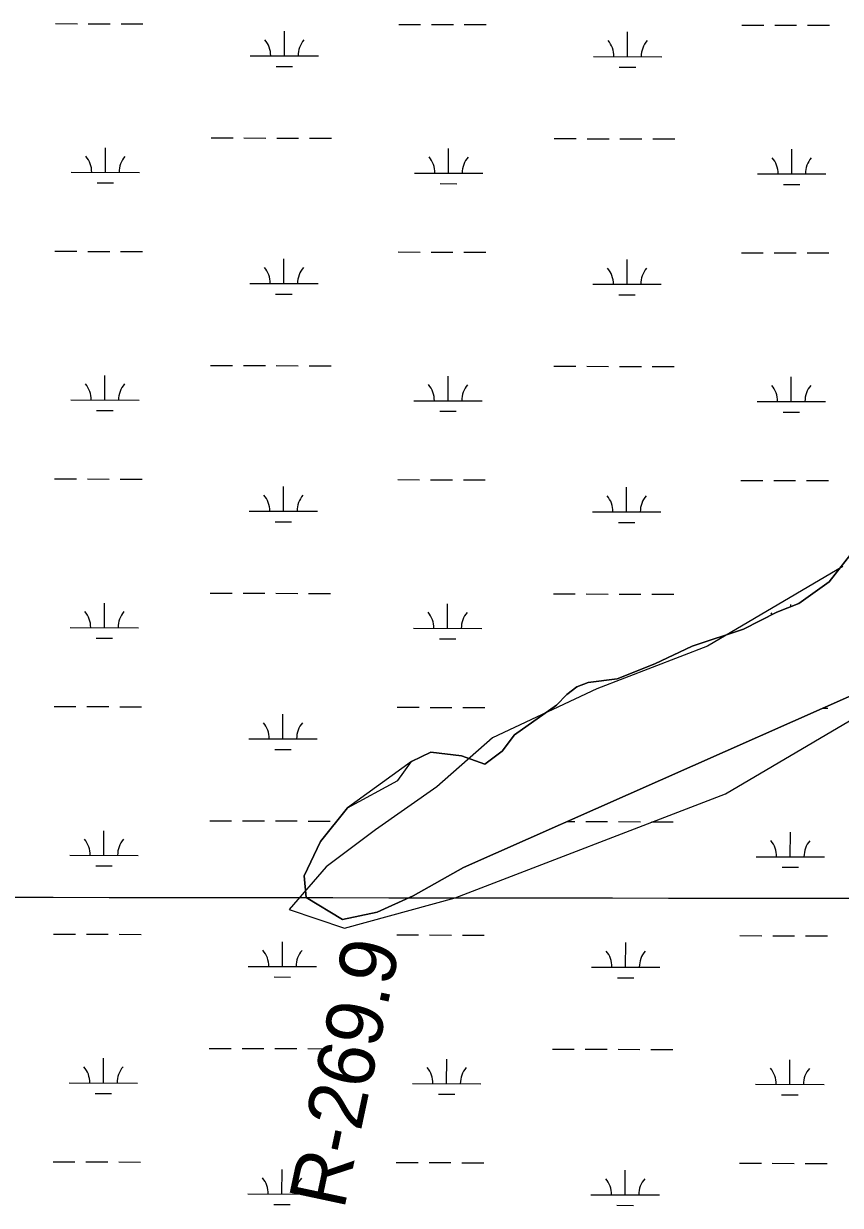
# Model space of a CAD drawing. Extents: x 3219052 to 3256913, y 800770 to 826146.
# Drawn here: x 3235140 to 3236335, y 817841 to 819568 of the extents above; entities that cross this region are included whole.
import ezdxf

# ---------------------------------------------------------------- set-up
doc = ezdxf.new("R2010")
doc.units = 0
for name, color, linetype in [('V-GRID-MAJR', 7, 'Continuous'), ('V-RIVR-RANG-IDEN', 7, 'Continuous'), ('V-SITE-VEGE', 7, 'Continuous'), ('V-TOPO-SHOR', 7, 'Continuous'), ('V-WETL-SWMP', 7, 'Continuous')]:
    doc.layers.add(name, color=color, linetype=linetype)

msp = doc.modelspace()

# ---------------------------------------------------------------- linework, layer by layer
at = {"layer": 'V-GRID-MAJR'}
msp.add_spline([(3223238.921, 818307.868), (3228474.772, 818299.872), (3233710.625, 818292.637), (3238946.4790000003, 818286.164), (3244182.3340000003, 818280.452), (3249418.1890000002, 818275.502), (3254654.045, 818271.314), (3254654.046, 818271.314)], degree=3, dxfattribs=at)
at = {"layer": 'V-SITE-VEGE'}
msp.add_lwpolyline([(3236358.7290000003, 818803.162), (3236318.039, 818751.6), (3236273.829, 818719.921), (3236241.593, 818707.291), (3236193.029, 818682.781), (3236117.8310000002, 818657.55), (3236063.301, 818631.861), (3236008.383, 818610.155), (3235965.8340000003, 818604.707), (3235949.123, 818598.393), (3235934.383, 818587.305), (3235919.631, 818571.448), (3235857.896, 818528.2880000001), (3235839.9420000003, 818504.091), (3235814.845, 818485.081), (3235780.693, 818497.498), (3235735.791, 818502.79), (3235707.5300000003, 818489.356), (3235613.924, 818421.243), (3235574.435, 818372.062), (3235550.4450000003, 818322.044), (3235553.14, 818290.634), (3235606.713, 818258.286), (3235657.225, 818268.878), (3235709.765, 818292.979), (3235783.419, 818334.115), (3236359.724, 818589.6950000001)], dxfattribs=at)
at = {"layer": 'V-TOPO-SHOR'}
msp.add_lwpolyline([(3236338.190335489, 818774.0942778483), (3236140.3128954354, 818657.7255548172), (3235978.4816379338, 818595.1813390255), (3235825.6148555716, 818523.6349916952), (3235744.6144999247, 818451.9380187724), (3235654.6496691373, 818389.2431773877), (3235582.670273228, 818335.4939829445), (3235528.638655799, 818272.7238287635), (3235609.431901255, 818245.6044649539), (3235771.2255023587, 818290.182074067), (3236166.810928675, 818442.0697900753), (3236364.688368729, 818558.4385131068)], dxfattribs=at)
at = {"layer": 'V-WETL-SWMP'}
for p, q in [((3235186.7248007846, 819567.5239450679), (3235218.724730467, 819567.4568760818)), ((3235234.7246953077, 819567.4233415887), (3235266.72462499, 819567.3562726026)), ((3235282.724589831, 819567.3227381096), (3235314.724519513, 819567.2556691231)), ((3235521.4707549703, 819520.3922870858), (3235521.5462053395, 819556.3921758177)), ((3235688.6316978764, 819566.4719931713), (3235720.6316275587, 819566.404924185)), ((3235736.6315923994, 819566.3713896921), (3235768.631522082, 819566.3043207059)), ((3235784.6314869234, 819566.270786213), (3235816.631416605, 819566.2037172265)), ((3236023.377652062, 819519.3403351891), (3236023.4531024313, 819555.3402239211)), ((3236190.5385949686, 819565.4200412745), (3236222.5385246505, 819565.3529722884)), ((3236238.5384894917, 819565.3194377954), (3236270.5384191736, 819565.2523688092)), ((3236286.538384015, 819565.2188343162), (3236318.538313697, 819565.1517653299)), ((3235471.4708648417, 819520.4970823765), (3235571.470645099, 819520.2874917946)), ((3235973.3777619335, 819519.4451304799), (3236073.3775421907, 819519.2355398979)), ((3235509.4384403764, 819504.9864856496), (3235533.438387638, 819504.9361839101)), ((3236011.345337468, 819503.934533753), (3236035.34528473, 819503.8842320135)), ((3235414.375339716, 819400.5455931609), (3235446.3752693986, 819400.4785241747)), ((3235462.3752342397, 819400.4449896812), (3235494.3751639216, 819400.3779206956)), ((3235510.375128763, 819400.3443862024), (3235542.375058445, 819400.2773172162)), ((3235558.375023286, 819400.2437827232), (3235590.3749529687, 819400.1767137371)), ((3235916.282236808, 819399.4936412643), (3235948.282166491, 819399.426572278)), ((3235964.2821313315, 819399.3930377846), (3235996.2820610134, 819399.325968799)), ((3236012.2820258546, 819399.2924343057), (3236044.281955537, 819399.2253653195)), ((3236060.2819203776, 819399.1918308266), (3236092.2818500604, 819399.1247618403)), ((3235259.6773321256, 819350.1277602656), (3235259.752782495, 819386.1276489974)), ((3235761.5842292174, 819349.075808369), (3235761.659679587, 819385.0756971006)), ((3236263.4911263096, 819348.0238564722), (3236263.566576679, 819384.023745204)), ((3235209.6774419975, 819350.2325555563), (3235309.6772222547, 819350.0229649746)), ((3235711.5843390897, 819349.1806036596), (3235811.5841193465, 819348.971013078)), ((3236213.4912361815, 819348.128651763), (3236313.4910164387, 819347.9190611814)), ((3235247.6450175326, 819334.7219588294), (3235271.644964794, 819334.67165709)), ((3235749.5519146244, 819333.6700069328), (3235773.551861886, 819333.6197051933)), ((3236251.458811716, 819332.6180550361), (3236275.458758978, 819332.5677532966)), ((3235186.027566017, 819234.8499732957), (3235218.0274957, 819234.7829043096)), ((3235234.0274605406, 819234.7493698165), (3235266.0273902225, 819234.6823008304)), ((3235282.0273550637, 819234.6487663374), (3235314.027284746, 819234.581697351)), ((3235687.934463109, 819233.7980213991), (3235719.9343927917, 819233.7309524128)), ((3235735.934357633, 819233.6974179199), (3235767.9342873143, 819233.6303489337)), ((3235783.9342521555, 819233.5968144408), (3235815.9341818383, 819233.5297454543)), ((3236189.841360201, 819232.7460695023), (3236221.8412898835, 819232.6790005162)), ((3236237.8412547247, 819232.6454660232), (3236269.8411844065, 819232.578397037)), ((3236285.8411492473, 819232.544862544), (3236317.84107893, 819232.4777935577)), ((3235520.773520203, 819187.7183153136), (3235520.848970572, 819223.7182040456)), ((3236022.6804172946, 819186.6663634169), (3236022.755867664, 819222.6662521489)), ((3235470.7736300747, 819187.8231106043), (3235570.773410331, 819187.6135200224)), ((3235972.6805271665, 819186.7711587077), (3236072.6803074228, 819186.5615681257)), ((3235508.7412056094, 819172.3125138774), (3235532.741152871, 819172.2622121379)), ((3236010.648102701, 819171.2605619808), (3236034.6480499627, 819171.2102602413)), ((3235258.980097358, 819017.4537884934), (3235259.0555477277, 819053.4536772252)), ((3235413.678104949, 819067.8716213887), (3235445.678034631, 819067.8045524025)), ((3235461.677999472, 819067.771017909), (3235493.6779291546, 819067.7039489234)), ((3235509.6778939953, 819067.6704144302), (3235541.6778236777, 819067.603345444)), ((3235557.677788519, 819067.569810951), (3235589.6777182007, 819067.5027419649)), ((3235760.8869944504, 819016.4018365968), (3235760.9624448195, 819052.4017253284)), ((3235915.585002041, 819066.8196694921), (3235947.584931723, 819066.7526005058)), ((3235963.5848965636, 819066.7190660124), (3235995.5848262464, 819066.6519970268)), ((3236011.584791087, 819066.6184625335), (3236043.5847207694, 819066.5513935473)), ((3236059.5846856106, 819066.5178590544), (3236091.5846152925, 819066.4507900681)), ((3236262.793891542, 819015.3498847), (3236262.8693419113, 819051.3497734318)), ((3235208.9802072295, 819017.5585837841), (3235308.9799874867, 819017.3489932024)), ((3235246.947782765, 819002.0479870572), (3235270.947730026, 819001.9976853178)), ((3235710.8871043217, 819016.5066318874), (3235810.886884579, 819016.2970413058)), ((3235748.854679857, 819000.9960351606), (3235772.854627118, 819000.9457334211)), ((3236212.7940014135, 819015.4546799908), (3236312.7937816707, 819015.2450894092)), ((3236250.7615769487, 818999.9440832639), (3236274.76152421, 818999.8937815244)), ((3235185.3303312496, 818902.1760015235), (3235217.330260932, 818902.1089325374)), ((3235233.330225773, 818902.0753980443), (3235265.330155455, 818902.0083290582)), ((3235281.3301202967, 818901.9747945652), (3235313.330049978, 818901.9077255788)), ((3235687.237228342, 818901.1240496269), (3235719.2371580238, 818901.0569806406)), ((3235735.237122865, 818901.0234461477), (3235767.237052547, 818900.9563771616)), ((3235783.2370173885, 818900.9228426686), (3235815.2369470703, 818900.8557736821)), ((3236189.1441254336, 818900.0720977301), (3236221.144055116, 818900.005028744)), ((3236237.1440199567, 818899.971494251), (3236269.143949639, 818899.9044252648)), ((3236285.14391448, 818899.8708907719), (3236317.143844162, 818899.8038217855)), ((3235520.0762854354, 818855.0443435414), (3235520.1517358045, 818891.0442322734)), ((3236021.983182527, 818853.9923916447), (3236022.0586328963, 818889.9922803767)), ((3235470.0763953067, 818855.1491388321), (3235570.076175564, 818854.9395482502)), ((3235971.9832923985, 818854.0971869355), (3236071.9830726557, 818853.8875963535)), ((3235508.0439708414, 818839.6385421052), (3235532.0439181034, 818839.5882403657)), ((3236009.950867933, 818838.5865902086), (3236033.950815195, 818838.5362884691)), ((3236318.0401024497, 818751.601859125), (3236358.7290990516, 818803.1647642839)), ((3236273.8281045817, 818719.9239186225), (3236318.0401024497, 818751.601859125)), ((3235412.980870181, 818735.1976496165), (3235444.980799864, 818735.1305806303)), ((3235460.9807647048, 818735.0970461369), (3235492.9806943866, 818735.0299771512)), ((3235508.980659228, 818734.996442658), (3235540.98058891, 818734.9293736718)), ((3235556.980553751, 818734.8958391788), (3235588.9804834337, 818734.8287701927)), ((3235914.887767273, 818734.1456977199), (3235946.887696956, 818734.0786287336)), ((3235962.8876617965, 818734.0450942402), (3235994.8875914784, 818733.9780252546)), ((3236010.8875563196, 818733.9444907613), (3236042.887486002, 818733.8774217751)), ((3236058.887450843, 818733.8438872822), (3236090.8873805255, 818733.7768182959)), ((3235258.2828625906, 818684.7798167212), (3235258.3583129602, 818720.779705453)), ((3235760.189759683, 818683.7278648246), (3235760.265210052, 818719.7277535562)), ((3236193.030107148, 818682.7839902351), (3236241.594105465, 818707.2939432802)), ((3236241.594105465, 818707.2939432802), (3236273.8281045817, 818719.9239186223)), ((3236262.165145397, 818715.3541199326), (3236262.172107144, 818718.6758016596)), ((3235208.282972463, 818684.884612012), (3235308.28275272, 818684.6750214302)), ((3235710.1898695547, 818683.8326601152), (3235810.189649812, 818683.6230695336)), ((3236117.8301089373, 818657.5530401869), (3236193.030107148, 818682.7839902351)), ((3235246.2505479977, 818669.374015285), (3235270.250495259, 818669.3237135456)), ((3235748.1574450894, 818668.3220633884), (3235772.1573923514, 818668.2717616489)), ((3236063.3001107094, 818631.8670896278), (3236117.8301089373, 818657.5530401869)), ((3236008.3831122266, 818610.1571319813), (3236063.3001107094, 818631.8670896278)), ((3235949.122113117, 818598.3971568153), (3235965.8351126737, 818604.7101444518)), ((3235965.8351126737, 818604.7101444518), (3236008.3831122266, 818610.1571319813)), ((3236359.724112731, 818589.6991460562), (3235783.419130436, 818334.1186401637)), ((3235919.6311149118, 818571.4492069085), (3235934.383113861, 818587.3081775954)), ((3235934.383113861, 818587.3081775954), (3235949.122113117, 818598.3971568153)), ((3235184.633096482, 818569.5020297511), (3235216.6330261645, 818569.434960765)), ((3235232.6329910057, 818569.4014262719), (3235264.6329206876, 818569.3343572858)), ((3235280.6328855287, 818569.3008227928), (3235312.632815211, 818569.2337538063)), ((3235686.5399935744, 818568.4500778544), (3235718.5399232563, 818568.3830088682)), ((3235734.5398880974, 818568.3494743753), (3235766.53981778, 818568.2824053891)), ((3235782.5397826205, 818568.2488708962), (3235814.539712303, 818568.1818019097)), ((3235857.8971178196, 818528.2922880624), (3235919.6311149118, 818571.4492069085)), ((3235519.379050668, 818522.370371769), (3235519.4545010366, 818558.3702605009)), ((3236308.8687295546, 818567.1457325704), (3236316.4466093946, 818567.1298500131)), ((3235469.3791605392, 818522.4751670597), (3235569.378940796, 818522.2655764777)), ((3235839.9411194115, 818504.0943324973), (3235857.8971178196, 818528.2922880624)), ((3235507.346736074, 818506.9645703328), (3235531.3466833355, 818506.9142685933)), ((3235707.5301206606, 818489.3583673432), (3235735.790119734, 818502.7943414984)), ((3235735.790119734, 818502.7943414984), (3235780.6941199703, 818497.5023480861)), ((3235814.845120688, 818485.0843681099), (3235839.9411194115, 818504.0943324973)), ((3235687.179122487, 818461.5894183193), (3235707.530120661, 818489.3583673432)), ((3235780.6941199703, 818497.5023480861), (3235814.845120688, 818485.0843681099)), ((3235613.9251252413, 818421.247495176), (3235687.179122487, 818461.5894183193)), ((3235574.435128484, 818372.0665856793), (3235613.9251252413, 818421.247495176)), ((3235412.2836354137, 818402.5236778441), (3235444.283565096, 818402.4566088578)), ((3235460.283529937, 818402.4230743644), (3235492.283459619, 818402.3560053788)), ((3235508.2834244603, 818402.3224708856), (3235540.283354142, 818402.2554018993)), ((3235556.2833189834, 818402.2218674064), (3235588.2832486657, 818402.1547984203)), ((3235935.193420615, 818401.4277057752), (3235946.190462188, 818401.4046569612)), ((3235962.1904270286, 818401.3711224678), (3235994.190356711, 818401.304053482)), ((3236010.1903215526, 818401.2705189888), (3236042.190251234, 818401.2034500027)), ((3236058.1902160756, 818401.1699155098), (3236090.1901457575, 818401.1028465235)), ((3235257.585627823, 818352.1058449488), (3235257.6610781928, 818388.1057336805)), ((3236261.3994220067, 818350.0019411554), (3236261.4748723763, 818386.0018298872)), ((3235550.445131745, 818322.0476766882), (3235574.435128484, 818372.0665856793)), ((3235207.585737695, 818352.2106402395), (3235307.585517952, 818352.0010496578)), ((3236211.3995318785, 818350.1067364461), (3236311.3993121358, 818349.8971458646)), ((3235245.5533132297, 818336.7000435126), (3235269.553260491, 818336.6497417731)), ((3235783.419130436, 818334.1186401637), (3235709.765133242, 818292.9827184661)), ((3236249.3671074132, 818334.5961397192), (3236273.3670546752, 818334.5458379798)), ((3235553.140133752, 818290.6367327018), (3235550.445131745, 818322.0476766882)), ((3235709.7651332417, 818292.9827184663), (3235657.226134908, 818268.8817649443)), ((3235606.713135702, 818258.2897871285), (3235553.140133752, 818290.6367327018)), ((3235657.226134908, 818268.8817649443), (3235606.713135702, 818258.2897871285)), ((3235183.9358617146, 818236.8280579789), (3235215.935791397, 818236.7609889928)), ((3235231.935756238, 818236.7274544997), (3235263.9356859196, 818236.6603855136)), ((3235279.9356507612, 818236.6268510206), (3235311.9355804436, 818236.5597820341)), ((3235518.6818159, 818189.6963999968), (3235518.7572662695, 818225.6962887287)), ((3235685.8427588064, 818235.7761060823), (3235717.8426884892, 818235.709037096)), ((3235733.84265333, 818235.6755026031), (3235765.842583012, 818235.6084336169)), ((3235781.842547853, 818235.574899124), (3235813.8424775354, 818235.5078301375)), ((3236020.5887129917, 818188.6444481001), (3236020.664163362, 818224.6443368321)), ((3236187.749655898, 818234.7241541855), (3236219.749585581, 818234.6570851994)), ((3236235.7495504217, 818234.6235507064), (3236267.7494801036, 818234.5564817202)), ((3236283.749444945, 818234.5229472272), (3236315.749374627, 818234.4558782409)), ((3235468.6819257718, 818189.8011952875), (3235568.6817060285, 818189.5916047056)), ((3235970.5888228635, 818188.7492433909), (3236070.5886031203, 818188.5396528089)), ((3235506.6495013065, 818174.2905985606), (3235530.6494485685, 818174.2402968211)), ((3236008.5563983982, 818173.238646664), (3236032.5563456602, 818173.1883449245)), ((3235411.5864006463, 818069.8497060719), (3235443.5863303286, 818069.7826370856)), ((3235459.5862951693, 818069.7491025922), (3235491.5862248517, 818069.6820336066)), ((3235507.5861896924, 818069.6484991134), (3235539.586119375, 818069.5814301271)), ((3235555.5860842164, 818069.5478956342), (3235587.5860138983, 818069.4808266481)), ((3235913.493297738, 818068.7977541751), (3235945.4932274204, 818068.730685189)), ((3235961.493192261, 818068.6971506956), (3235993.4931219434, 818068.6300817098)), ((3236009.4930867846, 818068.5965472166), (3236041.493016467, 818068.5294782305)), ((3236057.492981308, 818068.4959437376), (3236089.4929109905, 818068.4288747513)), ((3235256.888393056, 818019.4318731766), (3235256.963843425, 818055.4317619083)), ((3235758.795290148, 818018.37992128), (3235758.8707405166, 818054.3798100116)), ((3236260.7021872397, 818017.3279693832), (3236260.777637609, 818053.327858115)), ((3235206.8885029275, 818019.5366684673), (3235306.8882831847, 818019.3270778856)), ((3235708.7954000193, 818018.4847165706), (3235808.7951802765, 818018.275125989)), ((3236210.702297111, 818017.432764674), (3236310.7020773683, 818017.2231740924)), ((3235244.8560784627, 818004.0260717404), (3235268.856025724, 818003.975770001)), ((3235746.7629755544, 818002.9741198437), (3235770.762922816, 818002.9238181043)), ((3236248.669872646, 818001.922167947), (3236272.6698199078, 818001.8718662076)), ((3235183.2386269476, 817904.1540862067), (3235215.2385566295, 817904.0870172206)), ((3235231.2385214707, 817904.0534827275), (3235263.238451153, 817903.9864137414)), ((3235279.2384159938, 817903.9528792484), (3235311.238345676, 817903.8858102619)), ((3235685.1455240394, 817903.1021343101), (3235717.1454537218, 817903.0350653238)), ((3235733.1454185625, 817903.0015308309), (3235765.145348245, 817902.9344618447)), ((3235781.1453130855, 817902.9009273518), (3235813.145242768, 817902.8338583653)), ((3236187.052421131, 817902.0501824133), (3236219.0523508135, 817901.9831134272)), ((3236235.0523156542, 817901.9495789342), (3236267.0522453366, 817901.882509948)), ((3236283.0522101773, 817901.848975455), (3236315.0521398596, 817901.7819064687)), ((3235517.984581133, 817857.0224282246), (3235518.060031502, 817893.0223169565)), ((3236019.8914782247, 817855.9704763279), (3236019.966928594, 817891.9703650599)), ((3235467.9846910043, 817857.1272235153), (3235567.984471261, 817856.9176329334)), ((3235969.891588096, 817856.0752716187), (3236069.891368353, 817855.8656810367)), ((3235505.952266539, 817841.6166267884), (3235529.9522138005, 817841.5663250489)), ((3236007.859163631, 817840.5646748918), (3236031.8591108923, 817840.5143731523))]:
    msp.add_line(p, q, dxfattribs=at)
for centre, radius, start, end in [((3235466.228935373, 819520.9828727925), 35.24628790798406, 359.1080939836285, 40.65175231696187), ((3235576.714564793, 819520.7513048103), 35.246287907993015, 139.10808960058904, 180.65174793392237), ((3235968.135832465, 819519.9309208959), 35.24628790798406, 359.1080939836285, 40.65175231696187), ((3236078.6214618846, 819519.6993529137), 35.246287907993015, 139.10808960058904, 180.65174793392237), ((3235204.435512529, 819350.7183459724), 35.24628790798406, 359.1080939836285, 40.65175231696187), ((3235314.9211419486, 819350.4867779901), 35.246287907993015, 139.10808960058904, 180.65174793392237), ((3235706.3424096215, 819349.6663940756), 35.24628790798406, 359.1080939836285, 40.65175231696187), ((3235816.828039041, 819349.4348260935), 35.246287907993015, 139.10808960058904, 180.65174793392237), ((3236208.249306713, 819348.614442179), 35.24628790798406, 359.1080939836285, 40.65175231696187), ((3236318.7349361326, 819348.3828741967), 35.246287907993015, 139.10808960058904, 180.65174793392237), ((3235465.5317006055, 819188.3089010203), 35.24628790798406, 359.1080939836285, 40.65175231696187), ((3235576.017330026, 819188.0773330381), 35.246287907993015, 139.10808960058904, 180.65174793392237), ((3235967.4385976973, 819187.2569491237), 35.24628790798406, 359.1080939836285, 40.65175231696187), ((3236077.9242271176, 819187.0253811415), 35.246287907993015, 139.10808960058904, 180.65174793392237), ((3235203.7382777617, 819018.0443742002), 35.24628790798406, 359.1080939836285, 40.65175231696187), ((3235314.2239071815, 819017.8128062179), 35.246287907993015, 139.10808960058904, 180.65174793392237), ((3235705.6451748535, 819016.9924223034), 35.24628790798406, 359.1080939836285, 40.65175231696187), ((3235816.1308042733, 819016.7608543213), 35.246287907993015, 139.10808960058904, 180.65174793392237), ((3236207.5520719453, 819015.9404704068), 35.24628790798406, 359.1080939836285, 40.65175231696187), ((3236318.037701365, 819015.7089024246), 35.246287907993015, 139.10808960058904, 180.65174793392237), ((3235464.834465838, 818855.6349292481), 35.24628790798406, 359.1080939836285, 40.65175231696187), ((3235575.320095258, 818855.4033612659), 35.246287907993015, 139.10808960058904, 180.65174793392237), ((3235966.74136293, 818854.5829773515), 35.24628790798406, 359.1080939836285, 40.65175231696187), ((3236077.2269923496, 818854.3514093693), 35.246287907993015, 139.10808960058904, 180.65174793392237), ((3235203.0410429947, 818685.370402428), 35.24628790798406, 359.1080939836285, 40.65175231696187), ((3235313.526672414, 818685.1388344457), 35.246287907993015, 139.10808960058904, 180.65174793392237), ((3235704.9479400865, 818684.3184505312), 35.24628790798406, 359.1080939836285, 40.65175231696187), ((3235815.433569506, 818684.0868825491), 35.246287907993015, 139.10808960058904, 180.65174793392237), ((3236206.8548371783, 818683.2664986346), 35.24628790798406, 36.24824318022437, 40.65175231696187), ((3235464.1372310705, 818522.9609574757), 35.24628790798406, 359.1080939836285, 40.65175231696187), ((3235574.6228604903, 818522.7293894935), 35.246287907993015, 139.10808960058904, 180.65174793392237), ((3235202.3438082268, 818352.6964306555), 35.24628790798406, 359.1080939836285, 40.65175231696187), ((3235312.829437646, 818352.4648626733), 35.246287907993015, 139.10808960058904, 180.65174793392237), ((3236206.1576024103, 818350.5925268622), 35.24628790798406, 359.1080939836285, 40.65175231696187), ((3236316.6432318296, 818350.3609588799), 35.246287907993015, 139.10808960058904, 180.65174793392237), ((3235463.4399963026, 818190.2869857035), 35.24628790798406, 359.1080939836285, 40.65175231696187), ((3235573.925625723, 818190.0554177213), 35.246287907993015, 139.10808960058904, 180.65174793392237), ((3235965.3468933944, 818189.2350338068), 35.24628790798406, 359.1080939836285, 40.65175231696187), ((3236075.8325228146, 818189.0034658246), 35.246287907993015, 139.10808960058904, 180.65174793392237), ((3235201.6465734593, 818020.0224588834), 35.24628790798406, 359.1080939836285, 40.65175231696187), ((3235312.132202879, 818019.7908909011), 35.246287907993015, 139.10808960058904, 180.65174793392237), ((3235703.553470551, 818018.9705069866), 35.24628790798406, 359.1080939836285, 40.65175231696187), ((3235814.039099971, 818018.7389390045), 35.246287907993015, 139.10808960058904, 180.65174793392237), ((3236205.460367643, 818017.91855509), 35.24628790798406, 359.1080939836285, 40.65175231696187), ((3236315.9459970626, 818017.6869871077), 35.246287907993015, 139.10808960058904, 180.65174793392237), ((3235462.7427615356, 817857.6130139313), 35.24628790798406, 359.1080939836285, 40.65175231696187), ((3235573.2283909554, 817857.3814459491), 35.246287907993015, 139.10808960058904, 180.65174793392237), ((3235964.649658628, 817856.5610620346), 35.24628790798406, 359.1080939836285, 40.65175231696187), ((3236075.1352880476, 817856.3294940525), 35.246287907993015, 139.10808960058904, 180.65174793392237)]:
    msp.add_arc(centre, radius, start, end, dxfattribs=at)

# ---------------------------------------------------------------- texts
at = {"layer": 'V-RIVR-RANG-IDEN'}
msp.add_text('R-269.9', height=82.99999800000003, rotation=77.95882052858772, dxfattribs=at).set_placement((3235608.5853101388, 817832.8558478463))

doc.saveas('drawing.dxf')
